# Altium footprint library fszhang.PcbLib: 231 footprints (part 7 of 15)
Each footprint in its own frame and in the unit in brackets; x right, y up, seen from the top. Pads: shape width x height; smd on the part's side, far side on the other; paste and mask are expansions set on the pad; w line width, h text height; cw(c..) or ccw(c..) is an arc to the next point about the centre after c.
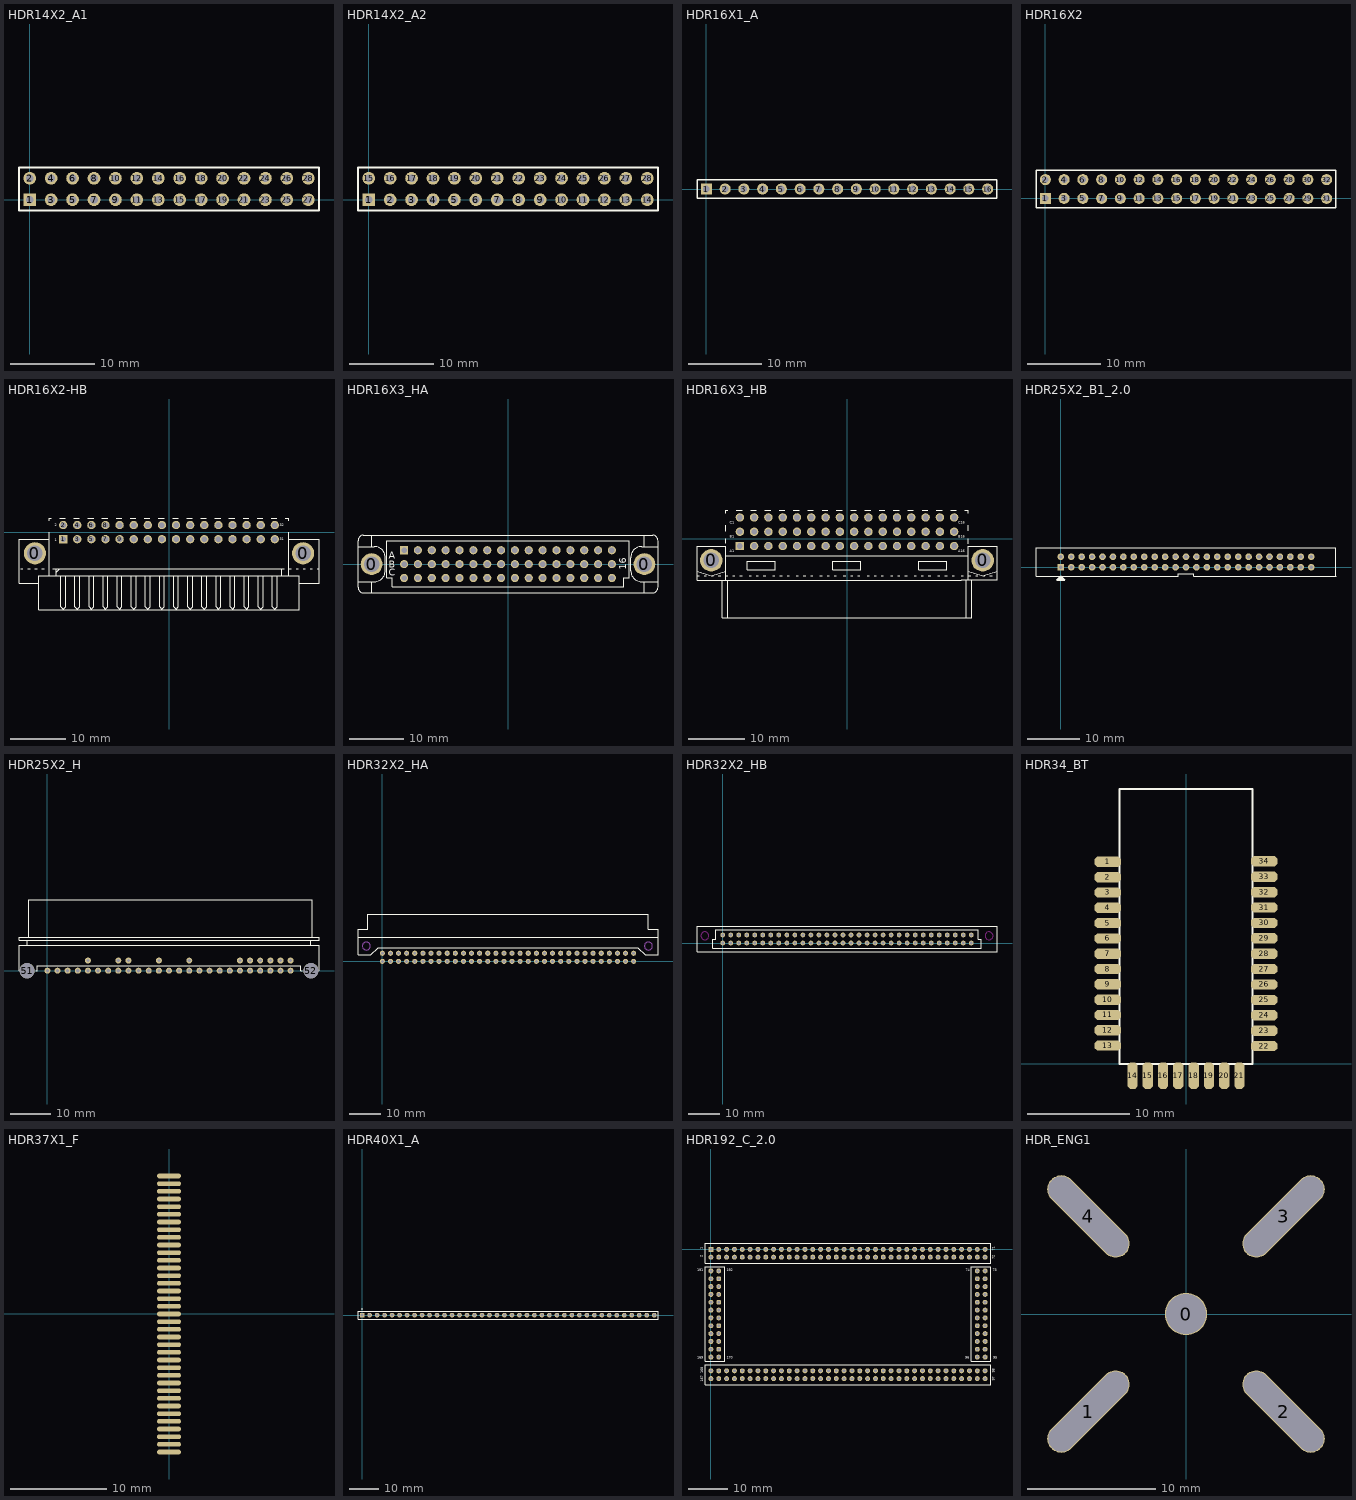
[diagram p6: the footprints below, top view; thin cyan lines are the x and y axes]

## HDR14X2_A1 [mm]
height 7
pads (28):
  rect 1.5x1.5 hole 0.9: 1(0,0)
  round 1.5 hole 0.9: 2(0,2.54) 3(2.54,0) 4(2.54,2.54) 5(5.08,0) 6(5.08,2.54) 7(7.62,0) 8(7.62,2.54) 9(10.16,0) 10(10.16,2.54) 11(12.7,0) 12(12.7,2.54) 13(15.24,0) 14(15.24,2.54) 15(17.78,0) 16(17.78,2.54) 17(20.32,0) 18(20.32,2.54) 19(22.86,0) 20(22.86,2.54) 21(25.4,0) 22(25.4,2.54) 23(27.94,0) 24(27.94,2.54) 25(30.48,0) 26(30.48,2.54) 27(33.02,0) 28(33.02,2.54)
Top Overlay:
  lines w0.2: -1.27,-1.27 34.29,-1.27 34.29,3.81 -1.27,3.81 -1.27,-1.27

## HDR14X2_A2 [mm]
height 7
pads (28):
  rect 1.5x1.5 hole 0.9: 1(0,0)
  round 1.5 hole 0.9: 2(2.54,0) 3(5.08,0) 4(7.62,0) 5(10.16,0) 6(12.7,0) 7(15.24,0) 8(17.78,0) 9(20.32,0) 10(22.86,0) 11(25.4,0) 12(27.94,0) 13(30.48,0) 14(33.02,0) 15(0,2.54) 16(2.54,2.54) 17(5.08,2.54) 18(7.62,2.54) 19(10.16,2.54) 20(12.7,2.54) 21(15.24,2.54) 22(17.78,2.54) 23(20.32,2.54) 24(22.86,2.54) 25(25.4,2.54) 26(27.94,2.54) 27(30.48,2.54) 28(33.02,2.54)
Top Overlay:
  lines w0.2: -1.27,-1.27 -1.27,3.81 34.29,3.81 34.29,-1.27 -1.27,-1.27

## HDR16X1_A [mm] "Connector; Header; 16 Position"
height 5.8
pads (16):
  rect 1.5x1.5 hole 0.9: 1(0,0)
  round 1.5 hole 0.9: 2(2.54,0) 3(5.08,0) 4(7.62,0) 5(10.16,0) 6(12.7,0) 7(15.24,0) 8(17.78,0) 9(20.32,0) 10(22.86,0) 11(25.4,0) 12(27.94,0) 13(30.48,0) 14(33.02,0) 15(35.56,0) 16(38.1,0)
Top Overlay:
  lines w0.2: -1.27,-1.27 -1.27,1.27 0.635,1.27 39.37,1.27 39.37,-1.27 -1.27,-1.27

## HDR16X2 [mm] "Connector; Header; 16x2 Position"
height 1.2
pads (32):
  rect 1.5x1.5 hole 0.9: 1(0,0)
  round 1.5 hole 0.9: 2(0,2.54) 3(2.54,0) 4(2.54,2.54) 5(5.08,0) 6(5.08,2.54) 7(7.62,0) 8(7.62,2.54) 9(10.16,0) 10(10.16,2.54) 11(12.7,0) 12(12.7,2.54) 13(15.24,0) 14(15.24,2.54) 15(17.78,0) 16(17.78,2.54) 17(20.32,0) 18(20.32,2.54) 19(22.86,0) 20(22.86,2.54) 21(25.4,0) 22(25.4,2.54) 23(27.94,0) 24(27.94,2.54) 25(30.48,0) 26(30.48,2.54) 27(33.02,0) 28(33.02,2.54) 29(35.56,0) 30(35.56,2.54) 31(38.1,0) 32(38.1,2.54)
Top Overlay:
  lines w0.2: -1.27,-1.27 39.37,-1.27 39.37,3.81 -1.27,3.81 -1.27,-1.27

## HDR16X2-HB [mm]
height 8.6
pads (34):
  round 4 hole 2.8: 0(-24.13,-3.81) 0(24.13,-3.81)
  rect 1.5x1.5 hole 1: 1(-19.05,-1.27)
  round 1.5 hole 1: 2(-19.05,1.27) 3(-16.51,-1.27) 4(-16.51,1.27) 5(-13.97,-1.27) 6(-13.97,1.27) 7(-11.43,-1.27) 8(-11.43,1.27) 9(-8.89,-1.27) 10(-8.89,1.27) 11(-6.35,-1.27) 12(-6.35,1.27) 13(-3.81,-1.27) 14(-3.81,1.27) 15(-1.27,-1.27) 16(-1.27,1.27) 17(1.27,-1.27) 18(1.27,1.27) 19(3.81,-1.27) 20(3.81,1.27) 21(6.35,-1.27) 22(6.35,1.27) 23(8.89,-1.27) 24(8.89,1.27) 25(11.43,-1.27) 26(11.43,1.27) 27(13.97,-1.27) 28(13.97,1.27) 29(16.51,-1.27) 30(16.51,1.27) 31(19.05,-1.27) 32(19.05,1.27)
Top Overlay:
  lines w0.2: -27,-6.57 -26.924,-6.57 ; -26.67,-6.57 -26.289,-6.57 ; -25.4,-6.57 -25.019,-6.57 ; -24.13,-6.57 -23.749,-6.57 ; -23.45,-7.874 -23.45,-9.21 ; -23.45,-7.84 -20.32,-7.84 ; -22.86,-6.57 -22.479,-6.57 ; -21.59,-7.84 -21.59,0 ; -21.59,-1.27 -27,-1.27 -27,-9.21 -23.45,-9.21 ; -21.59,2.032 -21.59,2.54 -21.209,2.54 ; -20.955,-6.57 20.701,-6.57 ; -20.32,-7.205 -19.685,-6.57 ; -19.685,2.54 -18.669,2.54 ; -19.473,-7.84 -19.473,-13.427 -19.05,-13.85 -18.627,-13.427 -18.627,-7.84 ; -17.145,2.54 -16.129,2.54 ; -16.933,-7.84 -16.933,-13.427 -16.51,-13.85 -16.087,-13.427 -16.087,-7.84 ; -14.605,2.54 -13.589,2.54 ; -14.393,-7.84 -14.393,-13.427 -13.97,-13.85 -13.547,-13.427 -13.547,-7.84 ; -12.065,2.54 -11.049,2.54 ; -11.853,-7.84 -11.853,-13.427 -11.43,-13.85 -11.007,-13.427 -11.007,-7.84 ; -9.525,2.54 -8.509,2.54 ; -9.313,-7.84 -9.313,-13.427 -8.89,-13.85 -8.467,-13.427 -8.467,-7.84 ; -6.985,2.54 -5.969,2.54 ; -6.773,-7.84 -6.773,-13.427 -6.35,-13.85 -5.927,-13.427 -5.927,-7.84 ; -4.445,2.54 -3.429,2.54 ; -4.233,-7.84 -4.233,-13.427 -3.81,-13.85 -3.387,-13.427 -3.387,-7.84 ; -1.905,2.54 -0.889,2.54 ; -1.693,-7.84 -1.693,-13.427 -1.27,-13.85 -0.847,-13.427 -0.847,-7.84 ; 0.635,2.54 1.651,2.54 ; 0.847,-7.84 0.847,-13.427 1.27,-13.85 1.693,-13.427 1.693,-7.84 ; 3.175,2.54 4.191,2.54 ; 3.387,-7.84 3.387,-13.427 3.81,-13.85 4.233,-13.427 4.233,-7.84 ; 5.715,2.54 6.731,2.54 ; 5.927,-7.84 5.927,-13.427 6.35,-13.85 6.773,-13.427 6.773,-7.84 ; 8.255,2.54 9.271,2.54 ; 8.467,-7.84 8.467,-13.427 8.89,-13.85 9.313,-13.427 9.313,-7.84 ; 10.795,2.54 11.811,2.54 ; 11.007,-7.84 11.007,-13.427 11.43,-13.85 11.853,-13.427 11.853,-7.84 ; 13.335,2.54 14.351,2.54 ; 13.547,-7.84 13.547,-13.427 13.97,-13.85 14.393,-13.427 14.393,-7.84 ; 15.875,2.54 16.891,2.54 ; 16.087,-7.84 16.087,-13.427 16.51,-13.85 16.933,-13.427 16.933,-7.84 ; 18.415,2.54 19.431,2.54 ; 18.627,-7.84 18.627,-13.427 19.05,-13.85 19.473,-13.427 19.473,-7.84 ; 20.955,2.54 21.59,2.54 21.59,2.032 ; 21.59,-7.84 21.59,0 ; 21.59,-6.57 21.971,-6.57 ; 21.59,-1.27 27,-1.27 27,-9.21 23.45,-9.21 ; 22.86,-6.57 23.241,-6.57 ; 24.13,-6.57 24.511,-6.57 ; 25.4,-6.57 25.781,-6.57 ; 26.67,-6.57 27,-6.57 ; -23.45,-9.21 -23.45,-14.01 23.45,-14.01 23.45,-9.565 23.45,-8.803 23.45,-7.84 20.32,-7.84 ; -20.32,-7.84 20.32,-7.84 ; -20.32,-7.84 -20.32,-6.57 20.32,-6.57 20.32,-7.84
  text "32" at 19.939,0.889 h0.8
  text "31" at 19.939,-1.651 h0.8
  text "1" at -20.574,-1.778 h0.8
  text "2" at -20.574,0.889 h0.8

## HDR16X3_HA [mm]
height 10
pads (50):
  round 4 hole 2.8: 0(-25,0) 0(25,0)
  rect 1.5x1.5 hole 1: A1(-19.05,2.54)
  round 1.5 hole 1: A2(-16.51,2.54) A3(-13.97,2.54) A4(-11.43,2.54) A5(-8.89,2.54) A6(-6.35,2.54) A7(-3.81,2.54) A8(-1.27,2.54) A9(1.27,2.54) A10(3.81,2.54) A11(6.35,2.54) A12(8.89,2.54) A13(11.43,2.54) A14(13.97,2.54) A15(16.51,2.54) A16(19.05,2.54) B1(-19.05,0) B2(-16.51,0) B3(-13.97,0) B4(-11.43,0) B5(-8.89,0) B6(-6.35,0) B7(-3.81,0) B8(-1.27,0) B9(1.27,0) B10(3.81,0) B11(6.35,0) B12(8.89,0) B13(11.43,0) B14(13.97,0) B15(16.51,0) B16(19.05,0) C1(-19.05,-2.54) C2(-16.51,-2.54) C3(-13.97,-2.54) C4(-11.43,-2.54) C5(-8.89,-2.54) C6(-6.35,-2.54) C7(-3.81,-2.54) C8(-1.27,-2.54) C9(1.27,-2.54) C10(3.81,-2.54) C11(6.35,-2.54) C12(8.89,-2.54) C13(11.43,-2.54) C14(13.97,-2.54) C15(16.51,-2.54) C16(19.05,-2.54)
Top Overlay:
  lines w0.2: -27.5,-3.2 -24.5,-3.2 ccw(c-24.5,-1.2) -22.5,-1.2 -22.5,1.2 ccw(c-24.5,1.2) -24.5,3.2 -27.5,3.2 ; -25,-5.25 -25,-3.2 ; -25,3.2 -25,5.3 ; 25,-5.25 25,-3.2 ; 25,3.2 25,5.3 ; 26.497,-5.25 22.5,-5.25 -22.5,-5.25 -26.5,-5.25 cw(c-26.5,-4.25) -27.5,-4.25 -27.5,3.2 ; 26.5,-5.25 ccw(c26.5,-4.25) 27.5,-4.25 27.5,3.2 ; 27.5,-3.2 24.5,-3.2 cw(c24.5,-1.2) 22.5,-1.2 22.5,1.2 cw(c24.5,1.2) 24.5,3.2 27.5,3.2 ; -27.5,3.2 -27.5,4.3 cw(c-26.5,4.3) -26.5,5.3 26.5,5.3 cw(c26.5,4.3) 27.5,4.3 27.5,3.2 ; -22.2,-2.54 -22.2,4.25 22.2,4.25 22.2,-2.54 21.225,-2.54 21.225,-4.178 -21.225,-4.178 -21.225,-2.54 -22.2,-2.54
  text "B" at -21.844,-0.635 h1.27
  text "A" at -21.844,1.016 h1.27
  text "C" at -21.844,-2.159 h1.27
  text "16" at 21.717,-1.016 h1.27

## HDR16X3_HB [mm]
height 10
pads (50):
  round 4 hole 2.8: 0(-24.13,-3.81) 0(24.13,-3.81)
  rect 1.5x1.5 hole 1: A1(-19.05,-1.27)
  round 1.5 hole 1: A2(-16.51,-1.27) A3(-13.97,-1.27) A4(-11.43,-1.27) A5(-8.89,-1.27) A6(-6.35,-1.27) A7(-3.81,-1.27) A8(-1.27,-1.27) A9(1.27,-1.27) A10(3.81,-1.27) A11(6.35,-1.27) A12(8.89,-1.27) A13(11.43,-1.27) A14(13.97,-1.27) A15(16.51,-1.27) A16(19.05,-1.27) B1(-19.05,1.27) B2(-16.51,1.27) B3(-13.97,1.27) B4(-11.43,1.27) B5(-8.89,1.27) B6(-6.35,1.27) B7(-3.81,1.27) B8(-1.27,1.27) B9(1.27,1.27) B10(3.81,1.27) B11(6.35,1.27) B12(8.89,1.27) B13(11.43,1.27) B14(13.97,1.27) B15(16.51,1.27) B16(19.05,1.27) C1(-19.05,3.81) C2(-16.51,3.81) C3(-13.97,3.81) C4(-11.43,3.81) C5(-8.89,3.81) C6(-6.35,3.81) C7(-3.81,3.81) C8(-1.27,3.81) C9(1.27,3.81) C10(3.81,3.81) C11(6.35,3.81) C12(8.89,3.81) C13(11.43,3.81) C14(13.97,3.81) C15(16.51,3.81) C16(19.05,3.81)
Top Overlay:
  lines w0.2: -26.67,-6.57 -26.289,-6.57 ; -26.67,-5.755 -24.13,-6.566 -21.59,-5.755 ; -25.4,-6.57 -25.019,-6.57 ; -24.13,-6.57 -23.749,-6.57 ; -22.86,-6.57 -22.479,-6.57 ; -21.59,-7.31 -21.59,-1.27 -26.67,-1.27 -26.67,-7.31 -22.92,-7.31 -20.32,-7.31 20.32,-7.31 ; -21.59,-6.57 -21.209,-6.57 ; -21.59,-3.01 21.59,-3.01 ; -21.59,-0.789 -21.59,0 ; -21.59,1.397 -21.59,2.413 ; -21.59,4.572 -21.59,5.08 -21.209,5.08 ; -20.32,-6.57 -19.939,-6.57 ; -19.685,5.08 -18.669,5.08 ; -19.05,-6.57 -18.669,-6.57 ; -17.399,-6.57 -17.018,-6.57 ; -17.145,5.08 -16.129,5.08 ; -16.129,-6.57 -15.748,-6.57 ; -14.859,-6.57 -14.478,-6.57 ; -14.605,5.08 -13.589,5.08 ; -13.208,-6.57 -12.827,-6.57 ; -12.065,5.08 -11.049,5.08 ; -11.938,-6.57 -11.557,-6.57 ; -10.668,-6.57 -10.287,-6.57 ; -9.525,5.08 -8.509,5.08 ; -9.017,-6.57 -8.636,-6.57 ; -7.747,-6.57 -7.366,-6.57 ; -6.985,5.08 -5.969,5.08 ; -6.477,-6.57 -6.096,-6.57 ; -4.826,-6.57 -4.445,-6.57 ; -4.445,5.08 -3.429,5.08 ; -3.556,-6.57 -3.175,-6.57 ; -2.286,-6.57 -1.905,-6.57 ; -1.905,5.08 -0.889,5.08 ; -0.635,-6.57 -0.254,-6.57 ; 0.635,-6.57 1.016,-6.57 ; 0.635,5.08 1.651,5.08 ; 1.905,-6.57 2.286,-6.57 ; 3.175,5.08 4.191,5.08 ; 3.556,-6.57 3.937,-6.57 ; 4.826,-6.57 5.207,-6.57 ; 5.715,5.08 6.731,5.08 ; 6.096,-6.57 6.477,-6.57 ; 7.747,-6.57 8.128,-6.57 ; 8.255,5.08 9.271,5.08 ; 9.017,-6.57 9.398,-6.57 ; 10.287,-6.57 10.668,-6.57 ; 10.795,5.08 11.811,5.08 ; 11.938,-6.57 12.319,-6.57 ; 13.208,-6.57 13.589,-6.57 ; 13.335,5.08 14.351,5.08 ; 14.478,-6.57 14.859,-6.57 ; 15.875,5.08 16.891,5.08 ; 16.129,-6.57 16.51,-6.57 ; 17.399,-6.57 17.78,-6.57 ; 18.415,5.08 19.431,5.08 ; 18.669,-6.57 19.05,-6.57 ; 20.32,-7.304 22.914,-7.304 26.67,-7.304 26.67,-1.27 21.59,-1.27 21.59,-7.304 ; 20.32,-6.57 20.701,-6.57 ; 20.955,5.08 21.59,5.08 21.59,4.572 ; 21.59,-5.755 24.13,-6.566 26.67,-5.755 ; 21.59,-0.865 21.59,0 ; 21.59,1.41 21.59,2.426 ; 24.13,-6.57 24.511,-6.57 ; 25.4,-6.57 25.781,-6.57 ; -22.2,-14.01 -22.2,-7.31 -21.225,-7.31 -21.225,-14.01 21.225,-14.01 21.225,-7.304 22.2,-7.304 22.2,-14.01 -22.2,-14.01 ; -17.755,-5.45 -12.755,-5.45 -12.755,-4.01 -17.755,-4.01 -17.755,-5.45 ; -2.515,-5.45 -2.515,-4.01 2.485,-4.01 2.485,-5.45 -2.515,-5.45 ; 12.755,-5.45 17.755,-5.45 17.755,-4.01 12.755,-4.01 12.755,-5.45 ; 21.59,-6.57 21.971,-6.57 21.59,-6.57 ; 22.86,-6.57 23.241,-6.57 22.86,-6.57
  text "C16" at 19.812,2.54 h0.8
  text "C1" at -20.828,2.54 h0.8
  text "B16" at 19.812,0 h0.8
  text "A16" at 19.812,-2.54 h0.8
  text "A1" at -20.828,-2.54 h0.8
  text "B1" at -20.828,0 h0.8

## HDR25X2_B1_2.0 [mm]
height 7
pads (50):
  rect 1.27x1.27 hole 0.711: 1(0,0)
  round 1.27 hole 0.711: 2(0,2) 3(2,0) 4(2,2) 5(4,0) 6(4,2) 7(6,0) 8(6,2) 9(8,0) 10(8,2) 11(10,0) 12(10,2) 13(12,0) 14(12,2) 15(14,0) 16(14,2) 17(16,0) 18(16,2) 19(18,0) 20(18,2) 21(20,0) 22(20,2) 23(22,0) 24(22,2) 25(24,0) 26(24,2) 27(26,0) 28(26,2) 29(28,0) 30(28,2) 31(30,0) 32(30,2) 33(32,0) 34(32,2) 35(34,0) 36(34,2) 37(36,0) 38(36,2) 39(38,0) 40(38,2) 41(40,0) 42(40,2) 43(42,0) 44(42,2) 45(44,0) 46(44,2) 47(46,0) 48(46,2) 49(48,0) 50(48,2)
Top Overlay:
  lines w0.178: -4.75,-1.75 22.5,-1.75 22.5,-1.25 25.5,-1.25 25.5,-1.75 52.75,-1.75 52.75,3.75 -4.75,3.75 -4.75,-1.75
  lines w0.25: 0,-2 -0.5,-2.5 0.5,-2.5 0.25,-2.25 ; 0,-2 0.25,-2.25 ; 0,-2 -0.25,-2.25 0.25,-2.25 ; 0,-2 0,-1.75 ; 0,-1.75 0.75,-2.5 -0.75,-2.5 0,-1.75
Bottom Overlay:
  text "50" at 48.26,4.064 h0.64
  text "49" at 48.26,-1.016 h0.64
  text "40" at 38.1,4.064 h0.64
  text "39" at 38.1,-1.016 h0.64
  text "30" at 27.94,4.064 h0.64
  text "29" at 27.94,-1.016 h0.64
  text "20" at 18.288,4.064 h0.64
  text "19" at 18.288,-1.016 h0.64
  text "10" at 8.128,4.064 h0.64
  text "9" at 8.128,-1.016 h0.64
  text "2" at 0,3.556 h0.64
  text "1" at 0,-1.016 h0.64

## HDR25X2_H [mm] "控制器接插件"
height 5.8
pads (38):
  round 1.5 hole 0.8: 1(0,0) 2(2.54,0) 3(5.08,0) 4(7.62,0) 5(10.16,0) 6(12.7,0) 7(15.24,0) 8(17.78,0) 9(20.32,0) 10(22.86,0) 11(25.4,0) 12(27.94,0) 13(30.48,0) 14(33.02,0) 15(35.56,0) 16(38.1,0) 17(40.64,0) 18(43.18,0) 19(45.72,0) 20(48.26,0) 21(50.8,0) 22(53.34,0) 23(55.88,0) 24(58.42,0) 25(60.96,0) 30(10.16,2.54) 33(17.78,2.54) 34(20.32,2.54) 37(27.94,2.54) 40(35.56,2.54) 45(48.26,2.54) 46(50.8,2.54) 47(53.34,2.54) 48(55.88,2.54) 49(58.42,2.54) 50(60.96,2.54)
  round 3.81 hole 3.81: 51(-5.08,0) 52(66.04,0)
Top Overlay:
  lines w0.2: -7.112,0 -7.112,6.35 68.072,6.35 68.072,0 ; -5.08,6.35 -5.08,7.62 ; -4.699,8.382 -4.699,17.78 66.421,17.78 66.421,8.382 ; -2.921,0 -2.54,0 -2.54,1.27 63.5,1.27 63.5,0 63.881,0 ; 66.04,6.35 66.04,7.62 ; -7.112,7.62 -7.112,8.382 68.072,8.382 68.072,7.62 -7.112,7.62

## HDR32X2_HA [mm] "Connector; Header; 30x2 Position"
height 5.8
pads (64):
  round 1.6 hole 0.9: a1(78.74,0) a2(76.2,0) a3(73.66,0) a4(71.12,0) a5(68.58,0) a6(66.04,0) a7(63.5,0) a8(60.96,0) a9(58.42,0) a10(55.88,0) a11(53.34,0) a12(50.8,0) a13(48.26,0) a14(45.72,0) a15(43.18,0) a16(40.64,0) a17(38.1,0) a18(35.56,0) a19(33.02,0) a20(30.48,0) a21(27.94,0) a22(25.4,0) a23(22.86,0) a24(20.32,0) a25(17.78,0) a26(15.24,0) a27(12.7,0) a28(10.16,0) a29(7.62,0) a30(5.08,0) a31(2.54,0) a32(0,0) b1(78.74,2.54) b2(76.2,2.54) b3(73.66,2.54) b4(71.12,2.54) b5(68.58,2.54) b6(66.04,2.54) b7(63.5,2.54) b8(60.96,2.54) b9(58.42,2.54) b10(55.88,2.54) b11(53.34,2.54) b12(50.8,2.54) b13(48.26,2.54) b14(45.72,2.54) b15(43.18,2.54) b16(40.64,2.54) b17(38.1,2.54) b18(35.56,2.54) b19(33.02,2.54) b20(30.48,2.54) b21(27.94,2.54) b22(25.4,2.54) b23(22.86,2.54) b24(20.32,2.54) b25(17.78,2.54) b26(15.24,2.54) b27(12.7,2.54) b28(10.16,2.54) b29(7.62,2.54) b30(5.08,2.54) b31(2.54,2.54) b32(0,2.54)
Top Overlay:
  lines w0.2: -7.63,7.62 86.37,7.62 ; -7.63,2 -7.63,10 -4.63,10 -4.63,14.8 83.37,14.8 83.37,10 86.37,10 86.37,2 82.37,2 80.07,4.3 -1.33,4.3 -3.63,2 -7.63,2
Mechanical 1:
  circle w0.2: c83.37,4.8 r1.25
  circle w0.2: c-5.04,4.8 r1.25
3D body: height 1.7, standoff 1, extent 7.239,0.254 8.001,4.318
3D body: height 1.7, standoff 1, extent 4.699,0.254 5.461,4.318
3D body: height 1.7, standoff 1, extent 2.159,0.254 2.921,4.318
3D body: height 1.7, standoff 1, extent -0.381,0.254 0.381,4.318
3D body: height 0.8, standoff 0, extent 78.359,1.905 79.121,4.318
3D body: height 0.8, standoff 0, extent 75.819,1.905 76.581,4.318
3D body: height 0.8, standoff 0, extent 60.579,1.905 61.341,4.318
3D body: height 0.8, standoff 0, extent 63.119,1.905 63.881,4.318
3D body: height 0.8, standoff 0, extent 65.659,1.905 66.421,4.318
3D body: height 0.8, standoff 0, extent 68.199,1.905 68.961,4.318
3D body: height 0.8, standoff 0, extent 70.739,1.905 71.501,4.318
3D body: height 0.8, standoff 0, extent 73.279,1.905 74.041,4.318
3D body: height 0.8, standoff 0, extent 45.339,1.905 46.101,4.318
3D body: height 0.8, standoff 0, extent 47.879,1.905 48.641,4.318
3D body: height 0.8, standoff 0, extent 50.419,1.905 51.181,4.318
3D body: height 0.8, standoff 0, extent 52.959,1.905 53.721,4.318
3D body: height 0.8, standoff 0, extent 55.499,1.905 56.261,4.318
3D body: height 0.8, standoff 0, extent 58.039,1.905 58.801,4.318
3D body: height 0.8, standoff 0, extent 30.099,1.905 30.861,4.318
3D body: height 0.8, standoff 0, extent 32.639,1.905 33.401,4.318
3D body: height 0.8, standoff 0, extent 35.179,1.905 35.941,4.318
3D body: height 0.8, standoff 0, extent 37.719,1.905 38.481,4.318
3D body: height 0.8, standoff 0, extent 40.259,1.905 41.021,4.318
3D body: height 0.8, standoff 0, extent 42.799,1.905 43.561,4.318
3D body: height 0.8, standoff 0, extent 14.859,1.905 15.621,4.318
3D body: height 0.8, standoff 0, extent 17.399,1.905 18.161,4.318
3D body: height 0.8, standoff 0, extent 19.939,1.905 20.701,4.318
3D body: height 0.8, standoff 0, extent 22.479,1.905 23.241,4.318
3D body: height 0.8, standoff 0, extent 25.019,1.905 25.781,4.318
3D body: height 0.8, standoff 0, extent 27.559,1.905 28.321,4.318
3D body: height 0.8, standoff 0, extent 12.319,1.905 13.081,4.318
3D body: height 0.8, standoff 0, extent 9.779,1.905 10.541,4.318
3D body: height 0.8, standoff 0, extent 7.239,1.905 8.001,4.318
3D body: height 0.8, standoff 0, extent 4.699,1.905 5.461,4.318
3D body: height 0.8, standoff 0, extent 2.159,1.905 2.921,4.318
3D body: height 0.8, standoff 0, extent -0.381,1.905 0.381,4.318
3D body: height 2, standoff 0, extent -7.62,2.032 86.36,7.62
3D body: height 2.2, standoff 0, extent -7.62,7.62 86.36,14.732
3D body: height 1.7, standoff 1, extent 9.779,0.254 10.541,4.318
3D body: height 1.7, standoff 1, extent 22.479,0.254 23.241,4.318
3D body: height 1.7, standoff 1, extent 12.319,0.254 13.081,4.318
3D body: height 1.7, standoff 1, extent 14.859,0.254 15.621,4.318
3D body: height 1.7, standoff 1, extent 17.399,0.254 18.161,4.318
3D body: height 1.7, standoff 1, extent 19.939,0.254 20.701,4.318
3D body: height 1.7, standoff 1, extent 35.179,0.254 35.941,4.318
3D body: height 1.7, standoff 1, extent 25.019,0.254 25.781,4.318
3D body: height 1.7, standoff 1, extent 27.559,0.254 28.321,4.318
3D body: height 1.7, standoff 1, extent 30.099,0.254 30.861,4.318
3D body: height 1.7, standoff 1, extent 32.639,0.254 33.401,4.318
3D body: height 1.7, standoff 1, extent 47.879,0.254 48.641,4.318
3D body: height 1.7, standoff 1, extent 37.719,0.254 38.481,4.318
3D body: height 1.7, standoff 1, extent 40.259,0.254 41.021,4.318
3D body: height 1.7, standoff 1, extent 42.799,0.254 43.561,4.318
3D body: height 1.7, standoff 1, extent 45.339,0.254 46.101,4.318
3D body: height 1.7, standoff 1, extent 60.579,0.254 61.341,4.318
3D body: height 1.7, standoff 1, extent 50.419,0.254 51.181,4.318
3D body: height 1.7, standoff 1, extent 52.959,0.254 53.721,4.318
3D body: height 1.7, standoff 1, extent 55.499,0.254 56.261,4.318
3D body: height 1.7, standoff 1, extent 58.039,0.254 58.801,4.318
3D body: height 1.7, standoff 1, extent 73.279,0.254 74.041,4.318
3D body: height 1.7, standoff 1, extent 63.119,0.254 63.881,4.318
3D body: height 1.7, standoff 1, extent 65.659,0.254 66.421,4.318
3D body: height 1.7, standoff 1, extent 68.199,0.254 68.961,4.318
3D body: height 1.7, standoff 1, extent 70.739,0.254 71.501,4.318
3D body: height 1.7, standoff 1, extent 75.819,0.254 76.581,4.318
3D body: height 1.7, standoff 1, extent 78.359,0.254 79.121,4.318
3D body: height 1.7, standoff 0, extent -0.381,-0.381 0.381,0.508
3D body: height 1.7, standoff 0, extent 2.159,-0.381 2.921,0.508
3D body: height 1.7, standoff 0, extent 4.699,-0.381 5.461,0.508
3D body: height 1.7, standoff 0, extent 12.319,-0.381 13.081,0.508
3D body: height 1.7, standoff 0, extent 9.779,-0.381 10.541,0.508
3D body: height 1.7, standoff 0, extent 7.239,-0.381 8.001,0.508
3D body: height 1.7, standoff 0, extent 19.939,-0.381 20.701,0.508
3D body: height 1.7, standoff 0, extent 17.399,-0.381 18.161,0.508
3D body: height 1.7, standoff 0, extent 14.859,-0.381 15.621,0.508
3D body: height 1.7, standoff 0, extent 27.559,-0.381 28.321,0.508
3D body: height 1.7, standoff 0, extent 25.019,-0.381 25.781,0.508
3D body: height 1.7, standoff 0, extent 22.479,-0.381 23.241,0.508
3D body: height 1.7, standoff 0, extent 35.179,-0.381 35.941,0.508
3D body: height 1.7, standoff 0, extent 32.639,-0.381 33.401,0.508
3D body: height 1.7, standoff 0, extent 30.099,-0.381 30.861,0.508
3D body: height 1.7, standoff 0, extent 42.799,-0.381 43.561,0.508
3D body: height 1.7, standoff 0, extent 40.259,-0.381 41.021,0.508
3D body: height 1.7, standoff 0, extent 37.719,-0.381 38.481,0.508
3D body: height 1.7, standoff 0, extent 50.419,-0.381 51.181,0.508
3D body: height 1.7, standoff 0, extent 47.879,-0.381 48.641,0.508
3D body: height 1.7, standoff 0, extent 45.339,-0.381 46.101,0.508
3D body: height 1.7, standoff 0, extent 58.039,-0.381 58.801,0.508
3D body: height 1.7, standoff 0, extent 55.499,-0.381 56.261,0.508
3D body: height 1.7, standoff 0, extent 52.959,-0.381 53.721,0.508
3D body: height 1.7, standoff 0, extent 65.659,-0.381 66.421,0.508
3D body: height 1.7, standoff 0, extent 63.119,-0.381 63.881,0.508
3D body: height 1.7, standoff 0, extent 60.579,-0.381 61.341,0.508
3D body: height 1.7, standoff 0, extent 73.279,-0.381 74.041,0.508
3D body: height 1.7, standoff 0, extent 70.739,-0.381 71.501,0.508
3D body: height 1.7, standoff 0, extent 68.199,-0.381 68.961,0.508
3D body: height 1.7, standoff 0, extent 78.359,-0.381 79.121,0.508
3D body: height 1.7, standoff 0, extent 75.819,-0.381 76.581,0.508

## HDR32X2_HB [mm] "Connector; Header; 30x2 Position"
height 5.8
pads (64):
  round 1.5 hole 0.9: a1(78.74,2.54) a2(76.2,2.54) a3(73.66,2.54) a4(71.12,2.54) a5(68.58,2.54) a6(66.04,2.54) a7(63.5,2.54) a8(60.96,2.54) a9(58.42,2.54) a10(55.88,2.54) a11(53.34,2.54) a12(50.8,2.54) a13(48.26,2.54) a14(45.72,2.54) a15(43.18,2.54) a16(40.64,2.54) a17(38.1,2.54) a18(35.56,2.54) a19(33.02,2.54) a20(30.48,2.54) a21(27.94,2.54) a22(25.4,2.54) a23(22.86,2.54) a24(20.32,2.54) a25(17.78,2.54) a26(15.24,2.54) a27(12.7,2.54) a28(10.16,2.54) a29(7.62,2.54) a30(5.08,2.54) a31(2.54,2.54) a32(0,2.54) b1(78.74,0) b2(76.2,0) b3(73.66,0) b4(71.12,0) b5(68.58,0) b6(66.04,0) b7(63.5,0) b8(60.96,0) b9(58.42,0) b10(55.88,0) b11(53.34,0) b12(50.8,0) b13(48.26,0) b14(45.72,0) b15(43.18,0) b16(40.64,0) b17(38.1,0) b18(35.56,0) b19(33.02,0) b20(30.48,0) b21(27.94,0) b22(25.4,0) b23(22.86,0) b24(20.32,0) b25(17.78,0) b26(15.24,0) b27(12.7,0) b28(10.16,0) b29(7.62,0) b30(5.08,0) b31(2.54,0) b32(0,0)
Top Overlay:
  lines w0.2: -8.13,-2.73 86.87,-2.73 86.87,5.27 -8.13,5.27 -8.13,-2.73 ; -3.13,-1.73 -3.13,1.27 -2.13,1.27 -2.13,4.27 80.87,4.27 80.87,1.27 81.87,1.27 81.87,-1.73 -3.13,-1.73
Keep-Out Layer:
  circle w0.2: c84.37,2.286 r1.25
  circle w0.2: c-5.63,2.286 r1.25

## HDR34_BT [mm] "蓝牙模块"
pads (34):
  oct 2.6x1 smd: 1(-7.62,19.697) 2(-7.62,18.205) 3(-7.62,16.712) 4(-7.62,15.22) 5(-7.62,13.728) 6(-7.62,12.236) 7(-7.62,10.743) 8(-7.62,9.251) 9(-7.62,7.759) 10(-7.62,6.267) 11(-7.62,4.774) 12(-7.62,3.282) 13(-7.62,1.79) 22(7.62,1.74) 23(7.62,3.241) 24(7.62,4.741) 25(7.62,6.242) 26(7.62,7.742) 27(7.62,9.243) 28(7.62,10.743) 29(7.62,12.244) 30(7.62,13.745) 31(7.62,15.245) 32(7.62,16.746) 33(7.62,18.246) 34(7.62,19.747)
  oct 1x2.6 smd: 14(-5.207,-1.143) 15(-3.719,-1.143) 16(-2.232,-1.143) 17(-0.744,-1.143) 18(0.744,-1.143) 19(2.232,-1.143) 20(3.719,-1.143) 21(5.207,-1.143)
Top Overlay:
  lines w0.2: -6.477,0 -6.477,26.797 6.477,26.797 6.477,0 0,0 -6.477,0

## HDR37X1_F [mm]
pads (37):
  oval 2.5x0.5 smd: 1(0,14.4) 2(0,13.6) 3(0,12.8) 4(0,12) 5(0,11.2) 6(0,10.4) 7(0,9.6) 8(0,8.8) 9(0,8) 10(0,7.2) 11(0,6.4) 12(0,5.6) 13(0,4.8) 14(0,4) 15(0,3.2) 16(0,2.4) 17(0,1.6) 18(0,0.8) 19(0,0) 20(0,-0.8) 21(0,-1.6) 22(0,-2.4) 23(0,-3.2) 24(0,-4) 25(0,-4.8) 26(0,-5.6) 27(0,-6.4) 28(0,-7.2) 29(0,-8) 30(0,-8.8) 31(0,-9.6) 32(0,-10.4) 33(0,-11.2) 34(0,-12) 35(0,-12.8) 36(0,-13.6) 37(0,-14.4)

## HDR40X1_A [mm] "Connector; Header; 30 Position"
height 1.2
pads (40):
  rect 1.6x1.6 hole 0.99: 1(0,0)
  round 1.6 hole 0.99: 2(2.54,0) 3(5.08,0) 4(7.62,0) 5(10.16,0) 6(12.7,0) 7(15.24,0) 8(17.78,0) 9(20.32,0) 10(22.86,0) 11(25.4,0) 12(27.94,0) 13(30.48,0) 14(33.02,0) 15(35.56,0) 16(38.1,0) 17(40.64,0) 18(43.18,0) 19(45.72,0) 20(48.26,0) 21(50.8,0) 22(53.34,0) 23(55.88,0) 24(58.42,0) 25(60.96,0) 26(63.5,0) 27(66.04,0) 28(68.58,0) 29(71.12,0) 30(73.66,0)
  round 1.6 hole 1: 31(76.2,0) 32(78.74,0) 33(81.28,0) 34(83.82,0) 35(86.36,0) 36(88.9,0) 37(91.44,0) 38(93.98,0) 39(96.52,0) 40(99.06,0)
Top Overlay:
  circle w0.25: c0,2.05 r0.125
  lines w0.2: -1.4,-1.4 -1.4,1.4 100.33,1.4 100.33,-1.4 -1.4,-1.4

## HDR192_C_2.0 [mm] "2440"
height 7
pads (192):
  rect 1.27x1.27 hole 0.7: 1(0,0)
  round 1.27 hole 0.7: 2(0,-2) 3(2,0) 4(2,-2) 5(4,0) 6(4,-2) 7(6,0) 8(6,-2) 9(8,0) 10(8,-2) 11(10,0) 12(10,-2) 13(12,0) 14(12,-2) 15(14,0) 16(14,-2) 17(16,0) 18(16,-2) 19(18,0) 20(18,-2) 21(20,0) 22(20,-2) 23(22,0) 24(22,-2) 25(24,0) 26(24,-2) 27(26,0) 28(26,-2) 29(28,0) 30(28,-2) 31(30,0) 32(30,-2) 33(32,0) 34(32,-2) 35(34,0) 36(34,-2) 37(36,0) 38(36,-2) 39(38,0) 40(38,-2) 41(40,0) 42(40,-2) 43(42,0) 44(42,-2) 45(44,0) 46(44,-2) 47(46,0) 48(46,-2) 49(48,0) 50(48,-2) 51(50,0) 52(50,-2) 53(52,0) 54(52,-2) 55(54,0) 56(54,-2) 57(56,0) 58(56,-2) 59(58,0) 60(58,-2) 61(60,0) 62(60,-2) 63(62,0) 64(62,-2) 65(64,0) 66(64,-2) 67(66,0) 68(66,-2) 69(68,0) 70(68,-2) 71(70,0) 72(70,-2) 73(70,-5.5) 74(68,-5.5) 75(70,-7.5) 76(68,-7.5) 77(70,-9.5) 78(68,-9.5) 79(70,-11.5) 80(68,-11.5) 81(70,-13.5) 82(68,-13.5) 83(70,-15.5) 84(68,-15.5) 85(70,-17.5) 86(68,-17.5) 87(70,-19.5) 88(68,-19.5) 89(70,-21.5) 90(68,-21.5) 91(70,-23.5) 92(68,-23.5) 93(70,-25.5) 94(68,-25.5) 95(70,-27.5) 96(68,-27.5) 97(70,-33) 98(70,-31) 99(68,-33) 100(68,-31) 101(66,-33) 102(66,-31) 103(64,-33) 104(64,-31) 105(62,-33) 106(62,-31) 107(60,-33) 108(60,-31) 109(58,-33) 110(58,-31) 111(56,-33) 112(56,-31) 113(54,-33) 114(54,-31) 115(52,-33) 116(52,-31) 117(50,-33) 118(50,-31) 119(48,-33) 120(48,-31) 121(46,-33) 122(46,-31) 123(44,-33) 124(44,-31) 125(42,-33) 126(42,-31) 127(40,-33) 128(40,-31) 129(38,-33) 130(38,-31) 131(36,-33) 132(36,-31) 133(34,-33) 134(34,-31) 135(32,-33) 136(32,-31) 137(30,-33) 138(30,-31) 139(28,-33) 140(28,-31) 141(26,-33) 142(26,-31) 143(24,-33) 144(24,-31) 145(22,-33) 146(22,-31) 147(20,-33) 148(20,-31) 149(18,-33) 150(18,-31) 151(16,-33) 152(16,-31) 153(14,-33) 154(14,-31) 155(12,-33) 156(12,-31) 157(10,-33) 158(10,-31) 159(8,-33) 160(8,-31) 161(6,-33) 162(6,-31) 163(4,-33) 164(4,-31) 165(2,-33) 166(2,-31) 167(0,-33) 168(0,-31) 169(0,-27.5) 170(2,-27.5) 171(0,-25.5) 172(2,-25.5) 173(0,-23.5) 174(2,-23.5) 175(0,-21.5) 176(2,-21.5) 177(0,-19.5) 178(2,-19.5) 179(0,-17.5) 180(2,-17.5) 181(0,-15.5) 182(2,-15.5) 183(0,-13.5) 184(2,-13.5) 185(0,-11.5) 186(2,-11.5) 187(0,-9.5) 188(2,-9.5) 189(0,-7.5) 190(2,-7.5) 191(0,-5.5) 192(2,-5.5)
Top Overlay:
  lines w0.2: -1.469,-3.5 -1.469,1.5 71.439,1.5 71.439,-3.5 -1.469,-3.5
  lines w0.254: -1.5,-34.5 71.5,-34.5 71.5,-29.5 -1.5,-29.5 -1.5,-34.5 ; -1.5,-28.5 -1.5,-4.5 3.5,-4.5 3.5,-28.5 -1.5,-28.5 ; 66.5,-28.5 71.5,-28.5 71.5,-4.5 66.5,-4.5 66.5,-28.5
  text "1" at -2.032,0 h0.64
  text "2" at -2.032,-2.032 h0.64
  text "71" at 72.4,-0.4 h0.64
  text "72" at 72.4,-2.5 h0.64
  text "74" at 65.024,-5.588 h0.64
  text "73" at 72,-5.6 h0.64
  text "95" at 72.136,-27.94 h0.64
  text "96" at 64.9,-27.9 h0.64
  text "97" at 72.4,-33.6 h0.64
  text "98" at 72.4,-31.5 h0.64
  text "167" at -2,-33.8 h0.64
  text "170" at 4.064,-27.94 h0.64
  text "169" at -3.556,-27.94 h0.64
  text "191" at -3.556,-5.588 h0.64
  text "192" at 4.064,-5.588 h0.64
  text "168" at -2,-31.6 h0.64

## HDR_ENG1 [mm] "舵机"
height 3
pads (5):
  round 3.3 hole 3.1: 0(0,0)
  oval 2.2x8.2 hole 2 slot 8 at 45 deg rot 135: 1(-7.62,-7.62) 3(7.62,7.62)
  oval 2.2x8.2 hole 2 slot 8 at 135 deg rot 45: 2(7.62,-7.62) 4(-7.62,7.62)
